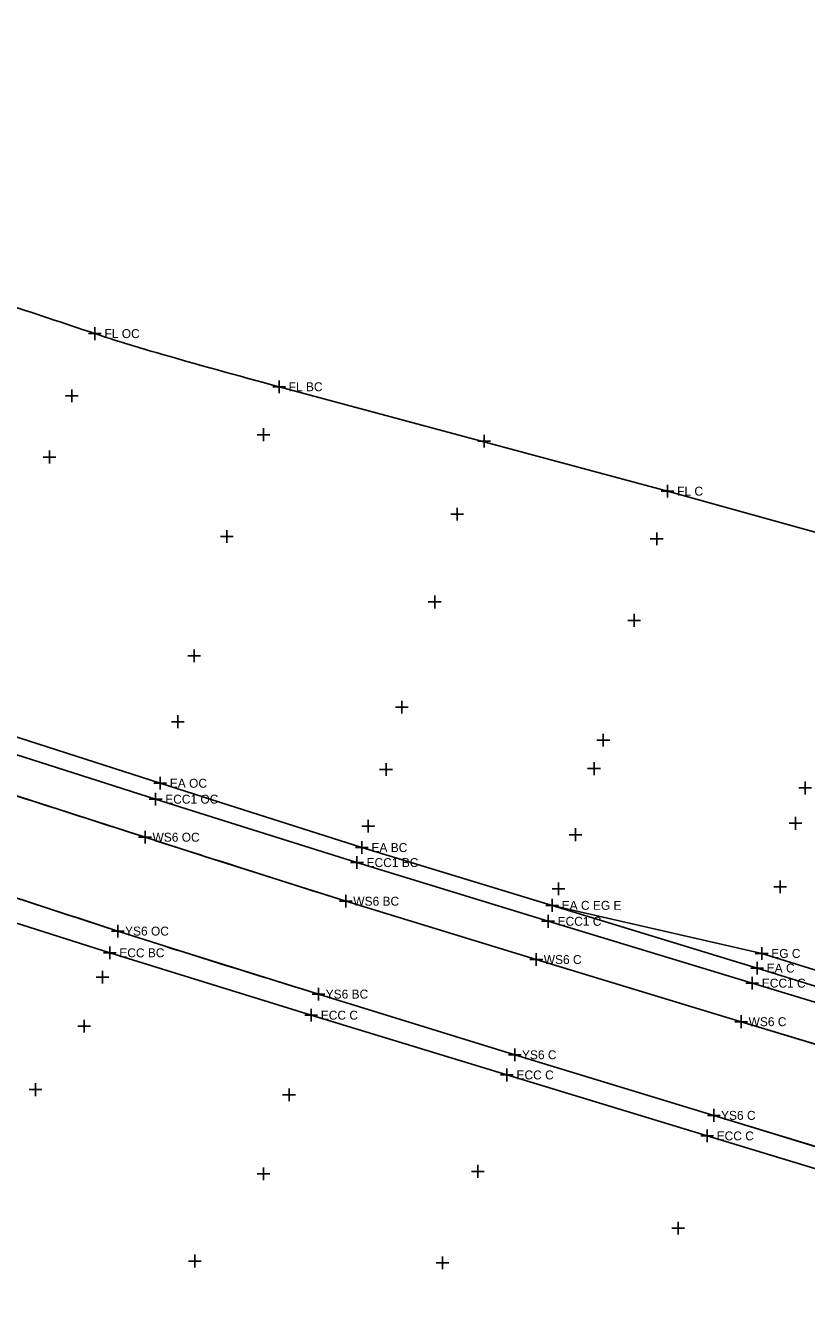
# Model space of a CAD drawing. Extents: x 1324236 to 1326110, y 459090 to 460782.
# Drawn here: x 1324746 to 1324868.3, y 460451 to 460651 of the extents above; entities that cross this region are included whole.
import ezdxf

# ---------------------------------------------------------------- set-up
doc = ezdxf.new("R2010")
doc.units = 0
for name, color, linetype in [('DR_X_Ditch', 7, 'Continuous'), ('DV_X_Property_Line', 7, 'Continuous'), ('PM_X_CL_Double_Solid', 7, 'Continuous'), ('PM_X_Edge_Line', 7, 'Continuous'), ('PV_X_Shoulder', 7, 'Continuous'), ('PV_X_Shoulder_Aggregate', 7, 'Continuous'), ('RW_X_CL', 7, 'Continuous'), ('RW_X_Esmt_SH', 7, 'Continuous')]:
    doc.layers.add(name, color=color, linetype=linetype)

msp = doc.modelspace()

# ---------------------------------------------------------------- linework, layer by layer
at = {"layer": 'DR_X_Ditch'}
for points in [[(1324889.88, 460485.35), (1324858.09, 460494.99), (1324826.02, 460504.72), (1324796.19, 460513.86), (1324775.41, 460520.46), (1324775.41, 460520.46), (1324764.75, 460523.88), (1324764.75, 460523.88), (1324734.72, 460533.54)], [(1324885.73, 460470.56), (1324853.81, 460480.32), (1324822.64, 460489.81), (1324791.92, 460499.31), (1324771.04, 460505.81), (1324771.04, 460505.81), (1324760.49, 460509.18), (1324760.49, 460509.18), (1324730.28, 460519.03)]]:
    msp.add_lwpolyline(points, dxfattribs=at)
at = {"layer": 'DV_X_Property_Line'}
for p, q in [((1324767.13, 460531.33), (1324767.13, 460533.33)), ((1324766.13, 460532.33), (1324768.13, 460532.33)), ((1324766.41, 460528.84), (1324766.41, 460530.84)), ((1324765.41, 460529.84), (1324767.41, 460529.84)), ((1324798.71, 460521.26), (1324798.71, 460523.26)), ((1324797.71, 460522.26), (1324799.71, 460522.26)), ((1324797.94, 460518.91), (1324797.94, 460520.91)), ((1324796.94, 460519.91), (1324798.94, 460519.91)), ((1324827.49, 460513.21), (1324829.49, 460513.21)), ((1324828.49, 460512.21), (1324828.49, 460514.21)), ((1324826.85, 460510.71), (1324828.85, 460510.71)), ((1324827.85, 460509.71), (1324827.85, 460511.71)), ((1324759.22, 460504.78), (1324759.22, 460506.78)), ((1324861.31, 460504.68), (1324861.31, 460506.68)), ((1324758.22, 460505.78), (1324760.22, 460505.78)), ((1324860.31, 460505.68), (1324862.31, 460505.68)), ((1324860.6, 460502.39), (1324860.6, 460504.39)), ((1324859.6, 460503.39), (1324861.6, 460503.39)), ((1324858.83, 460501.03), (1324860.83, 460501.03)), ((1324859.83, 460500.03), (1324859.83, 460502.03)), ((1324790.77, 460495.01), (1324790.77, 460497.01)), ((1324789.77, 460496.01), (1324791.77, 460496.01)), ((1324820.42, 460486.65), (1324822.42, 460486.65)), ((1324821.42, 460485.65), (1324821.42, 460487.65)), ((1324851.76, 460477.1), (1324853.76, 460477.1)), ((1324852.76, 460476.1), (1324852.76, 460478.1))]:
    msp.add_line(p, q, dxfattribs=at)
at = {"layer": 'PM_X_CL_Double_Solid'}
for p, q in [((1324846.57, 460578.07), (1324785.74, 460594.43)), ((1324877.64, 460569.41), (1324846.57, 460578.07))]:
    msp.add_line(p, q, dxfattribs=at)
for centre, radius, start, end in [((1329199.49, 473967.19), 14083.49, 251.487294, 251.612201), ((1324835.87, 460840.32), 250.35, 251.6122, 253.9076), ((1325042.29, 461555.84), 995.05, 253.90755, 255.05882)]:
    msp.add_arc(centre, radius, start, end, dxfattribs=at)
at = {"layer": 'PM_X_Edge_Line'}
for p, q in [((1324826.02, 460504.72), (1324796.19, 460513.86)), ((1324858.09, 460494.99), (1324826.02, 460504.72)), ((1324822.64, 460489.81), (1324791.92, 460499.31)), ((1324889.88, 460485.35), (1324858.09, 460494.99)), ((1324853.81, 460480.32), (1324822.64, 460489.81)), ((1324885.73, 460470.56), (1324853.81, 460480.32))]:
    msp.add_line(p, q, dxfattribs=at)
for centre, radius, start, end in [((1506453.84, 1025433.53), 593408.66, 252.16786365, 252.17090898), ((1326051.75, 464525.44), 4203.44, 252.17091, 252.32351), ((1329617.32, 475713.7), 15946.11, 252.32351, 252.401858), ((1380875.35, 632739.43), 181141.2, 251.9436678, 251.9537174), ((1325082.84, 461498.56), 1040.57, 251.95372, 252.56382), ((1325984.86, 464370.55), 4050.88, 252.56382, 252.87304)]:
    msp.add_arc(centre, radius, start, end, dxfattribs=at)
at = {"layer": 'PV_X_Shoulder'}
for points in [[(1324892.37, 460493.49), (1324860.6, 460503.39), (1324828.49, 460513.21), (1324798.71, 460522.26), (1324777.87, 460528.9), (1324767.13, 460532.33), (1324737.7, 460541.77), (1324736.57, 460542.13), (1324724.28, 460546.18), (1324705.87, 460552.49), (1324692.5, 460557.36), (1324676.12, 460563.81), (1324663.42, 460569.15), (1324646.7, 460576.57), (1324628.95, 460584.84), (1324618.08, 460590.25), (1324607.15, 460596.07), (1324589.72, 460605.76), (1324574.73, 460614.33), (1324571.84, 460616.11), (1324566.97, 460619.36), (1324545.31, 460634.03), (1324520.36, 460651)], [(1324891.71, 460491.37), (1324859.83, 460501.03), (1324827.85, 460510.71), (1324797.94, 460519.91), (1324777.14, 460526.43), (1324777.14, 460526.43), (1324766.41, 460529.84), (1324766.41, 460529.84), (1324736.79, 460539.31)], [(1324884.93, 460467.36), (1324852.76, 460477.1), (1324821.42, 460486.65), (1324790.77, 460496.01), (1324759.22, 460505.78), (1324738.54, 460512.37)]]:
    msp.add_lwpolyline(points, dxfattribs=at)
at = {"layer": 'PV_X_Shoulder_Aggregate'}
msp.add_lwpolyline([(1325286.15, 460376.13), (1325267.35, 460382.9), (1325236.36, 460392.86), (1325205.04, 460402.74), (1325175.07, 460412.61), (1325145.55, 460421.9), (1325113.81, 460432.03), (1325082.13, 460441.54), (1325051.05, 460449.76), (1325019.35, 460459.28), (1324987.54, 460468.89), (1324956.75, 460477.62), (1324924.35, 460486.71), (1324893.18, 460495.82), (1324861.31, 460505.68), (1324828.49, 460513.21)], dxfattribs=at)
at = {"layer": 'RW_X_CL'}
for p, q in [((1324752.28, 460593), (1324754.28, 460593)), ((1324753.28, 460592), (1324753.28, 460594)), ((1324782.31, 460586.92), (1324784.31, 460586.92)), ((1324783.31, 460585.92), (1324783.31, 460587.92)), ((1324817.84, 460584.92), (1324817.84, 460586.92)), ((1324749.8, 460582.42), (1324749.8, 460584.42)), ((1324816.84, 460585.92), (1324818.84, 460585.92)), ((1324748.8, 460583.42), (1324750.8, 460583.42)), ((1324812.64, 460574.47), (1324814.64, 460574.47)), ((1324813.64, 460573.47), (1324813.64, 460575.47)), ((1324776.56, 460570.97), (1324778.56, 460570.97)), ((1324777.56, 460569.97), (1324777.56, 460571.97)), ((1324843.87, 460570.62), (1324845.87, 460570.62)), ((1324844.87, 460569.62), (1324844.87, 460571.62)), ((1324809.11, 460560.72), (1324811.11, 460560.72)), ((1324810.11, 460559.72), (1324810.11, 460561.72)), ((1324841.34, 460556.84), (1324841.34, 460558.84)), ((1324840.34, 460557.84), (1324842.34, 460557.84)), ((1324772.46, 460551.3), (1324772.46, 460553.3)), ((1324771.46, 460552.3), (1324773.46, 460552.3)), ((1324804.97, 460543.26), (1324804.97, 460545.26)), ((1324769.88, 460540.97), (1324769.88, 460542.97)), ((1324803.97, 460544.26), (1324805.97, 460544.26)), ((1324768.88, 460541.97), (1324770.88, 460541.97)), ((1324835.51, 460539.07), (1324837.51, 460539.07)), ((1324836.51, 460538.07), (1324836.51, 460540.07)), ((1324801.49, 460534.49), (1324803.49, 460534.49)), ((1324802.49, 460533.49), (1324802.49, 460535.49)), ((1324834.06, 460534.62), (1324836.06, 460534.62)), ((1324835.06, 460533.62), (1324835.06, 460535.62)), ((1324868.13, 460530.59), (1324868.13, 460532.59)), ((1324867.13, 460531.59), (1324869.13, 460531.59)), ((1324799.7, 460524.62), (1324799.7, 460526.62)), ((1324866.6, 460525.06), (1324866.6, 460527.06)), ((1324764.75, 460522.88), (1324764.75, 460524.88)), ((1324798.7, 460525.62), (1324800.7, 460525.62)), ((1324832.14, 460523.28), (1324832.14, 460525.28)), ((1324865.6, 460526.06), (1324867.6, 460526.06)), ((1324763.75, 460523.88), (1324765.75, 460523.88)), ((1324831.14, 460524.28), (1324833.14, 460524.28)), ((1324829.48, 460514.79), (1324829.48, 460516.79)), ((1324864.2, 460515.12), (1324864.2, 460517.12)), ((1324796.19, 460512.86), (1324796.19, 460514.86)), ((1324828.48, 460515.79), (1324830.48, 460515.79)), ((1324863.2, 460516.12), (1324865.2, 460516.12)), ((1324795.19, 460513.86), (1324797.19, 460513.86)), ((1324759.49, 460509.18), (1324761.49, 460509.18)), ((1324760.49, 460508.18), (1324760.49, 460510.18)), ((1324825.02, 460504.72), (1324827.02, 460504.72)), ((1324826.02, 460503.72), (1324826.02, 460505.72)), ((1324758.09, 460500.97), (1324758.09, 460502.97)), ((1324757.09, 460501.97), (1324759.09, 460501.97)), ((1324790.92, 460499.31), (1324792.92, 460499.31)), ((1324791.92, 460498.31), (1324791.92, 460500.31)), ((1324755.22, 460493.3), (1324755.22, 460495.3)), ((1324857.09, 460494.99), (1324859.09, 460494.99)), ((1324858.09, 460493.99), (1324858.09, 460495.99)), ((1324754.22, 460494.3), (1324756.22, 460494.3)), ((1324822.64, 460488.81), (1324822.64, 460490.81)), ((1324821.64, 460489.81), (1324823.64, 460489.81)), ((1324747.61, 460483.35), (1324747.61, 460485.35)), ((1324787.3, 460482.53), (1324787.3, 460484.53)), ((1324746.61, 460484.35), (1324748.61, 460484.35)), ((1324786.3, 460483.53), (1324788.3, 460483.53)), ((1324853.81, 460479.32), (1324853.81, 460481.32)), ((1324852.81, 460480.32), (1324854.81, 460480.32)), ((1324816.87, 460470.55), (1324816.87, 460472.55)), ((1324782.29, 460471.15), (1324784.29, 460471.15)), ((1324783.29, 460470.15), (1324783.29, 460472.15)), ((1324815.87, 460471.55), (1324817.87, 460471.55)), ((1324847.24, 460462.67), (1324849.24, 460462.67)), ((1324848.24, 460461.67), (1324848.24, 460463.67)), ((1324772.56, 460456.51), (1324772.56, 460458.51)), ((1324771.56, 460457.51), (1324773.56, 460457.51)), ((1324810.33, 460457.21), (1324812.33, 460457.21)), ((1324811.33, 460456.21), (1324811.33, 460458.21))]:
    msp.add_line(p, q, dxfattribs=at)
at = {"layer": 'RW_X_Esmt_SH'}
for p, q in [((1324755.9, 460602.75), (1324757.9, 460602.75)), ((1324756.9, 460601.75), (1324756.9, 460603.75)), ((1324784.74, 460594.43), (1324786.74, 460594.43)), ((1324785.74, 460593.43), (1324785.74, 460595.43)), ((1324846.57, 460577.07), (1324846.57, 460579.07)), ((1324845.57, 460578.07), (1324847.57, 460578.07))]:
    msp.add_line(p, q, dxfattribs=at)

# ---------------------------------------------------------------- texts
at = {"layer": 'DV_X_Property_Line'}
for s, p in [('EA OC', (1324768.63, 460531.63)), ('ECC1 OC', (1324767.91, 460529.14)), ('EA BC', (1324800.21, 460521.56)), ('ECC1 BC', (1324799.44, 460519.21)), ('EA C EG E', (1324829.99, 460512.51)), ('ECC1 C', (1324829.35, 460510.01)), ('ECC BC', (1324760.72, 460505.08)), ('EG C', (1324862.81, 460504.98)), ('EA C', (1324862.1, 460502.69)), ('ECC1 C', (1324861.33, 460500.33)), ('ECC C', (1324792.27, 460495.31)), ('ECC C', (1324822.92, 460485.95)), ('ECC C', (1324854.26, 460476.4))]:
    msp.add_text(s, height=1.4, dxfattribs=at).set_placement(p)
at = {"layer": 'RW_X_CL'}
for s, p in [('WS6 OC', (1324765.92, 460523.18)), ('WS6 BC', (1324797.36, 460513.16)), ('YS6 OC', (1324761.62, 460508.48)), ('WS6 C', (1324827.18, 460504.02)), ('YS6 BC', (1324793.04, 460498.61)), ('WS6 C', (1324859.26, 460494.29)), ('YS6 C', (1324823.77, 460489.11)), ('YS6 C', (1324854.94, 460479.62))]:
    msp.add_text(s, height=1.4, dxfattribs=at).set_placement(p)
at = {"layer": 'RW_X_Esmt_SH'}
for s, p in [('FL OC', (1324758.4, 460602.05)), ('FL BC', (1324787.24, 460593.73)), ('FL C', (1324848.07, 460577.37))]:
    msp.add_text(s, height=1.4, dxfattribs=at).set_placement(p)

doc.saveas('drawing.dxf')
